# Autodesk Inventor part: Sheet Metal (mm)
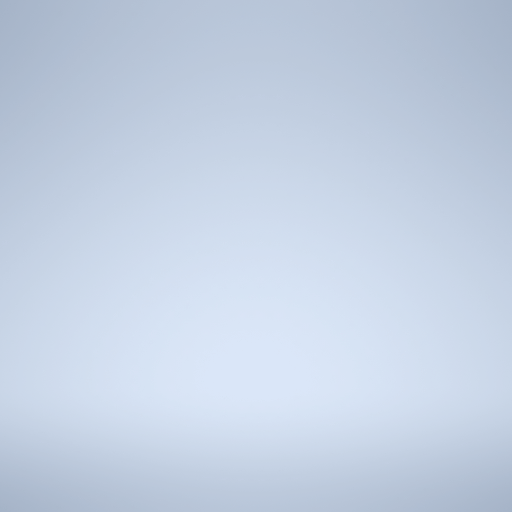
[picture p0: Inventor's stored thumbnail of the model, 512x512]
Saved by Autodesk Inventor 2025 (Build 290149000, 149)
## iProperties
Created: 2024-02
Part Number: Sheet Metal (mm)
Material: Všeobecné
Document SubType Name: Sheet Metal
Density: 1 g/cm^3
Sheet Metal Rule: Výchozí_mm
Appearance: Výchozí
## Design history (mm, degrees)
other parameters: "Tloušťka" = 0.5, "PoloměrOhybu" = 0.5 (= Tloušťka), "ŠířkaVýštipu" = 0.5 (= Tloušťka), "HloubkaVýštipu" = 0.25 (= 0.5 x Tloušťka), "VelikostRohovéhoVýštipu" = 2 (= 4 x Tloušťka), "SeamGap" = 0.01, "MinimálníZbytek" = 1 (= 2 x Tloušťka), "PřechodovýPoloměr" = 0.5 (= PoloměrOhybu), "VelikostJacobihoPoloměru" = 0.5 (= PoloměrOhybu), "VelikostMezery" = 0.5 (= Tloušťka)
